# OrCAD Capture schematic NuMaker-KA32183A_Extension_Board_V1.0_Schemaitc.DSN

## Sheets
1 System_Block_Diagram: title: Block Diagram; rev: v1.1; note: NuMaker-M483SG-KA32183A
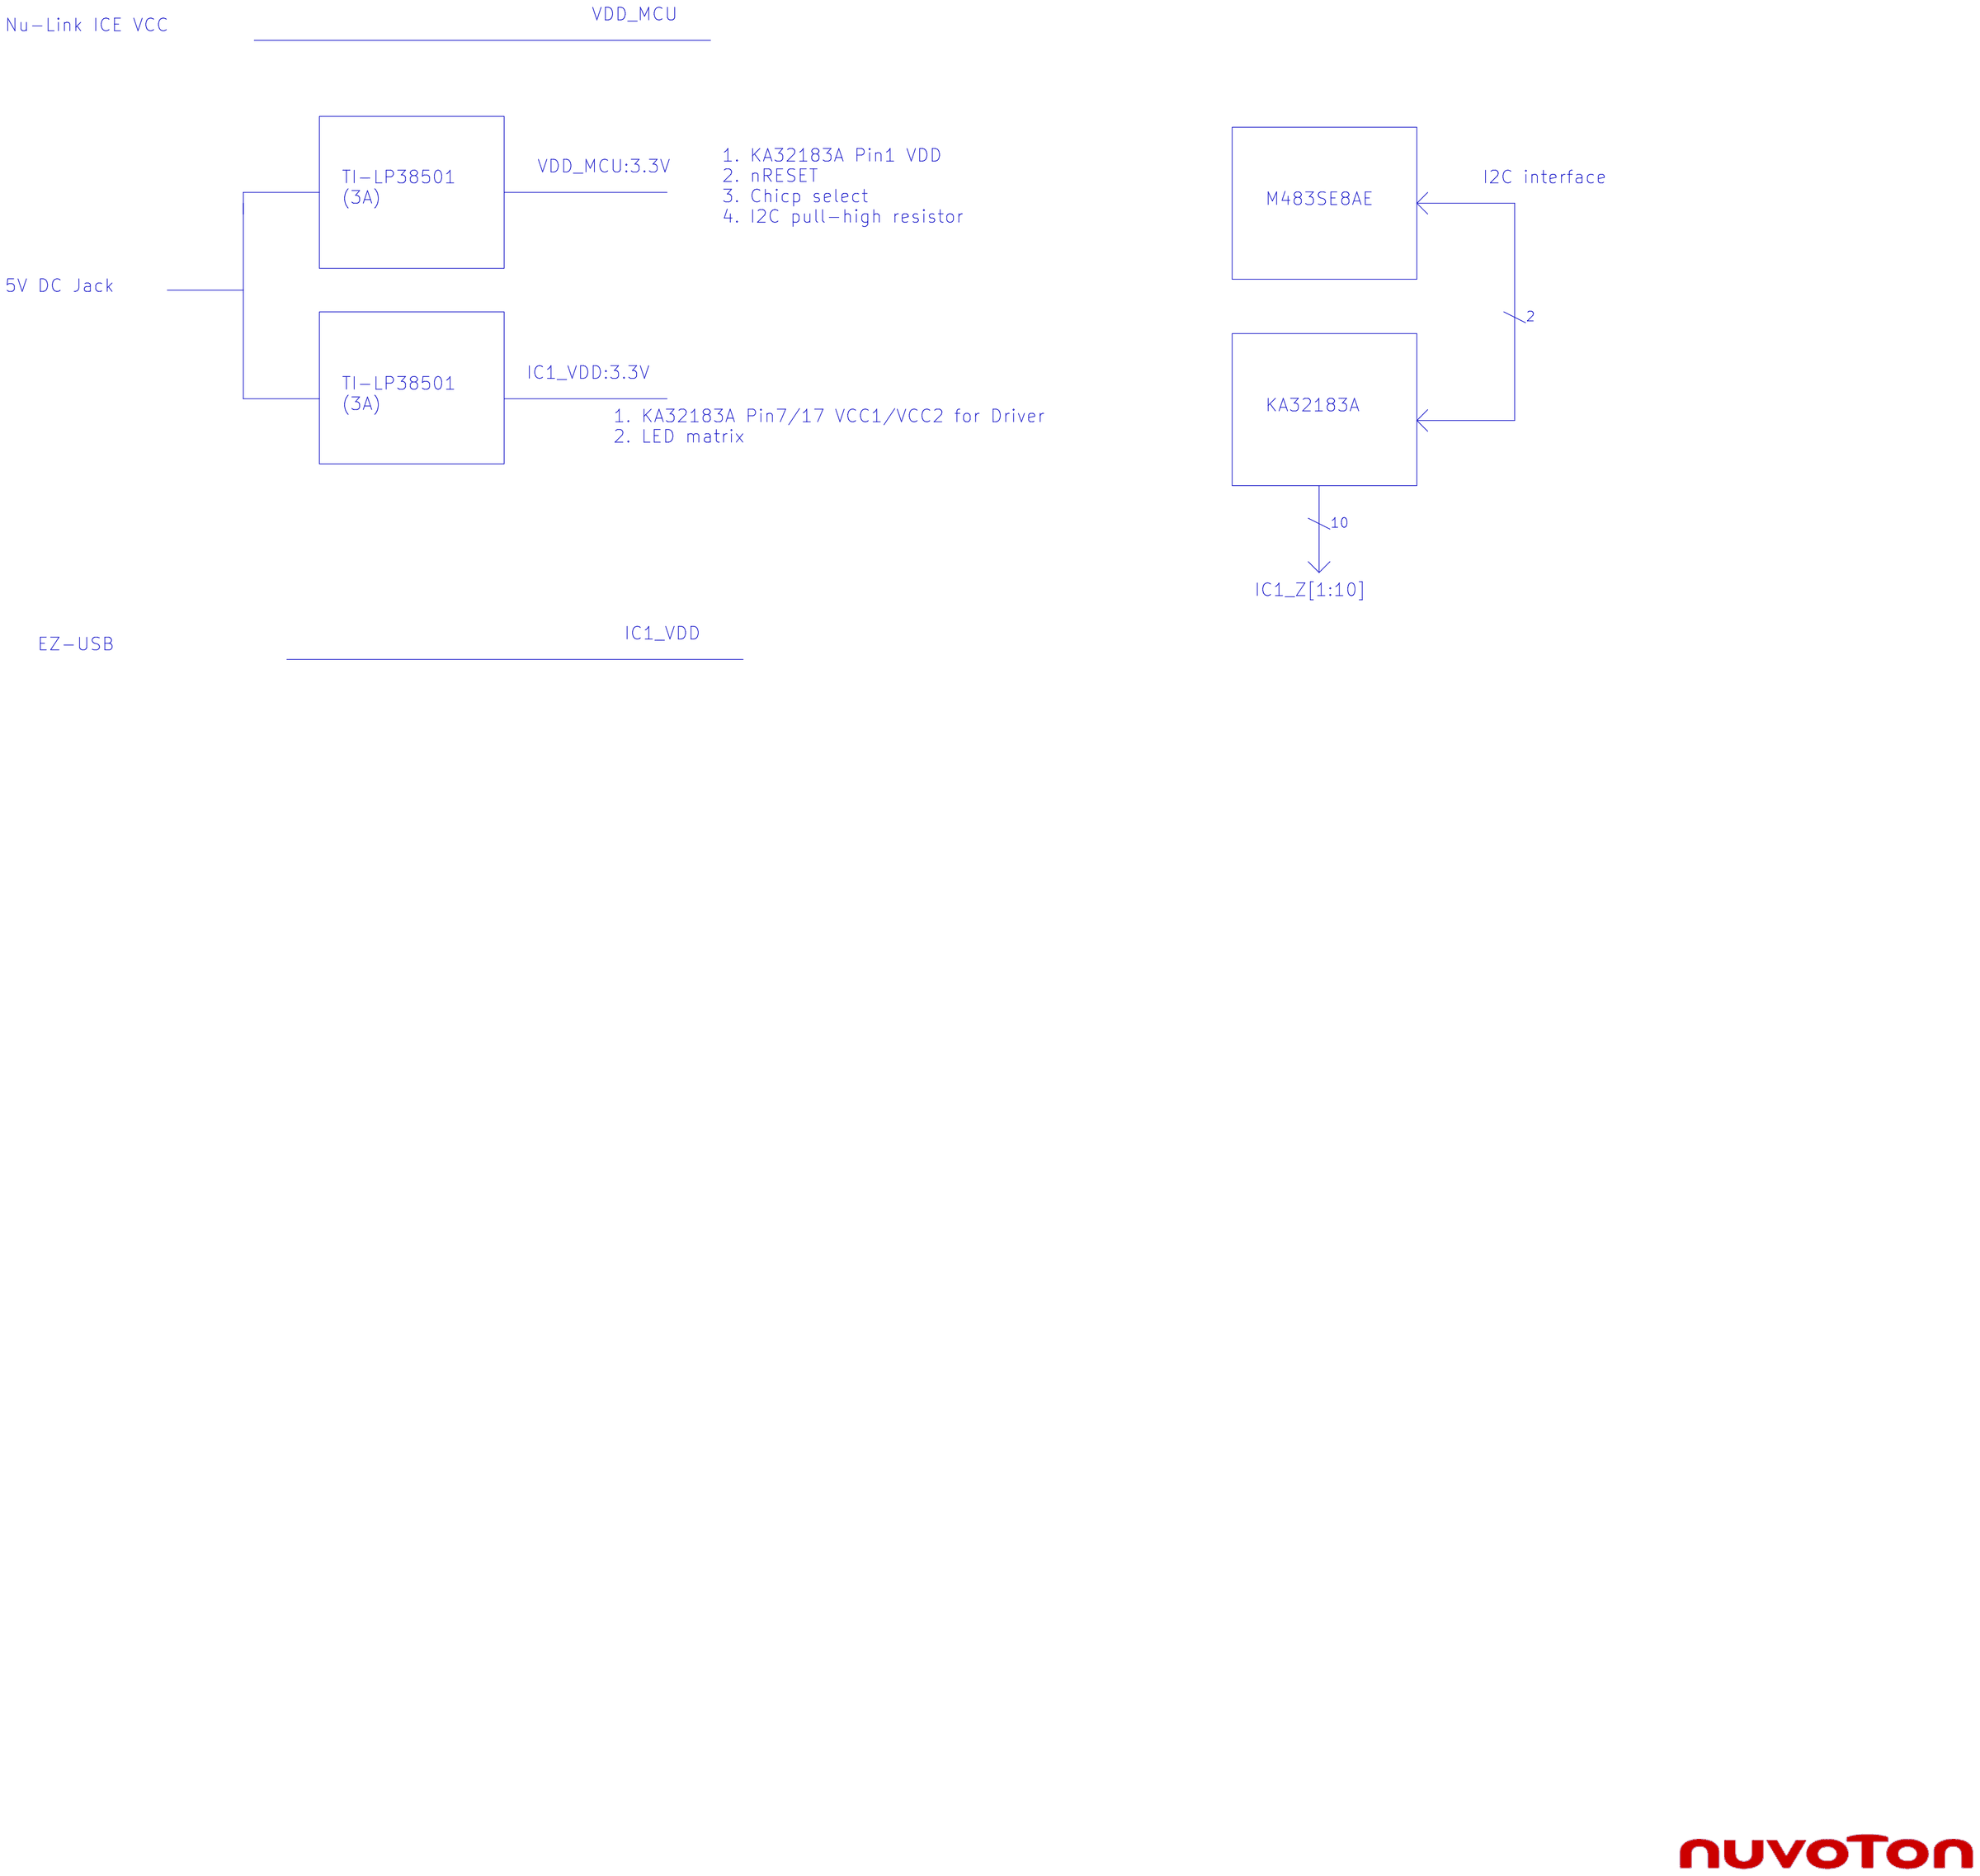
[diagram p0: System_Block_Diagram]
2 Power: size Custom; title: Power Block; note: NuMaker-M483KG-KA32183A
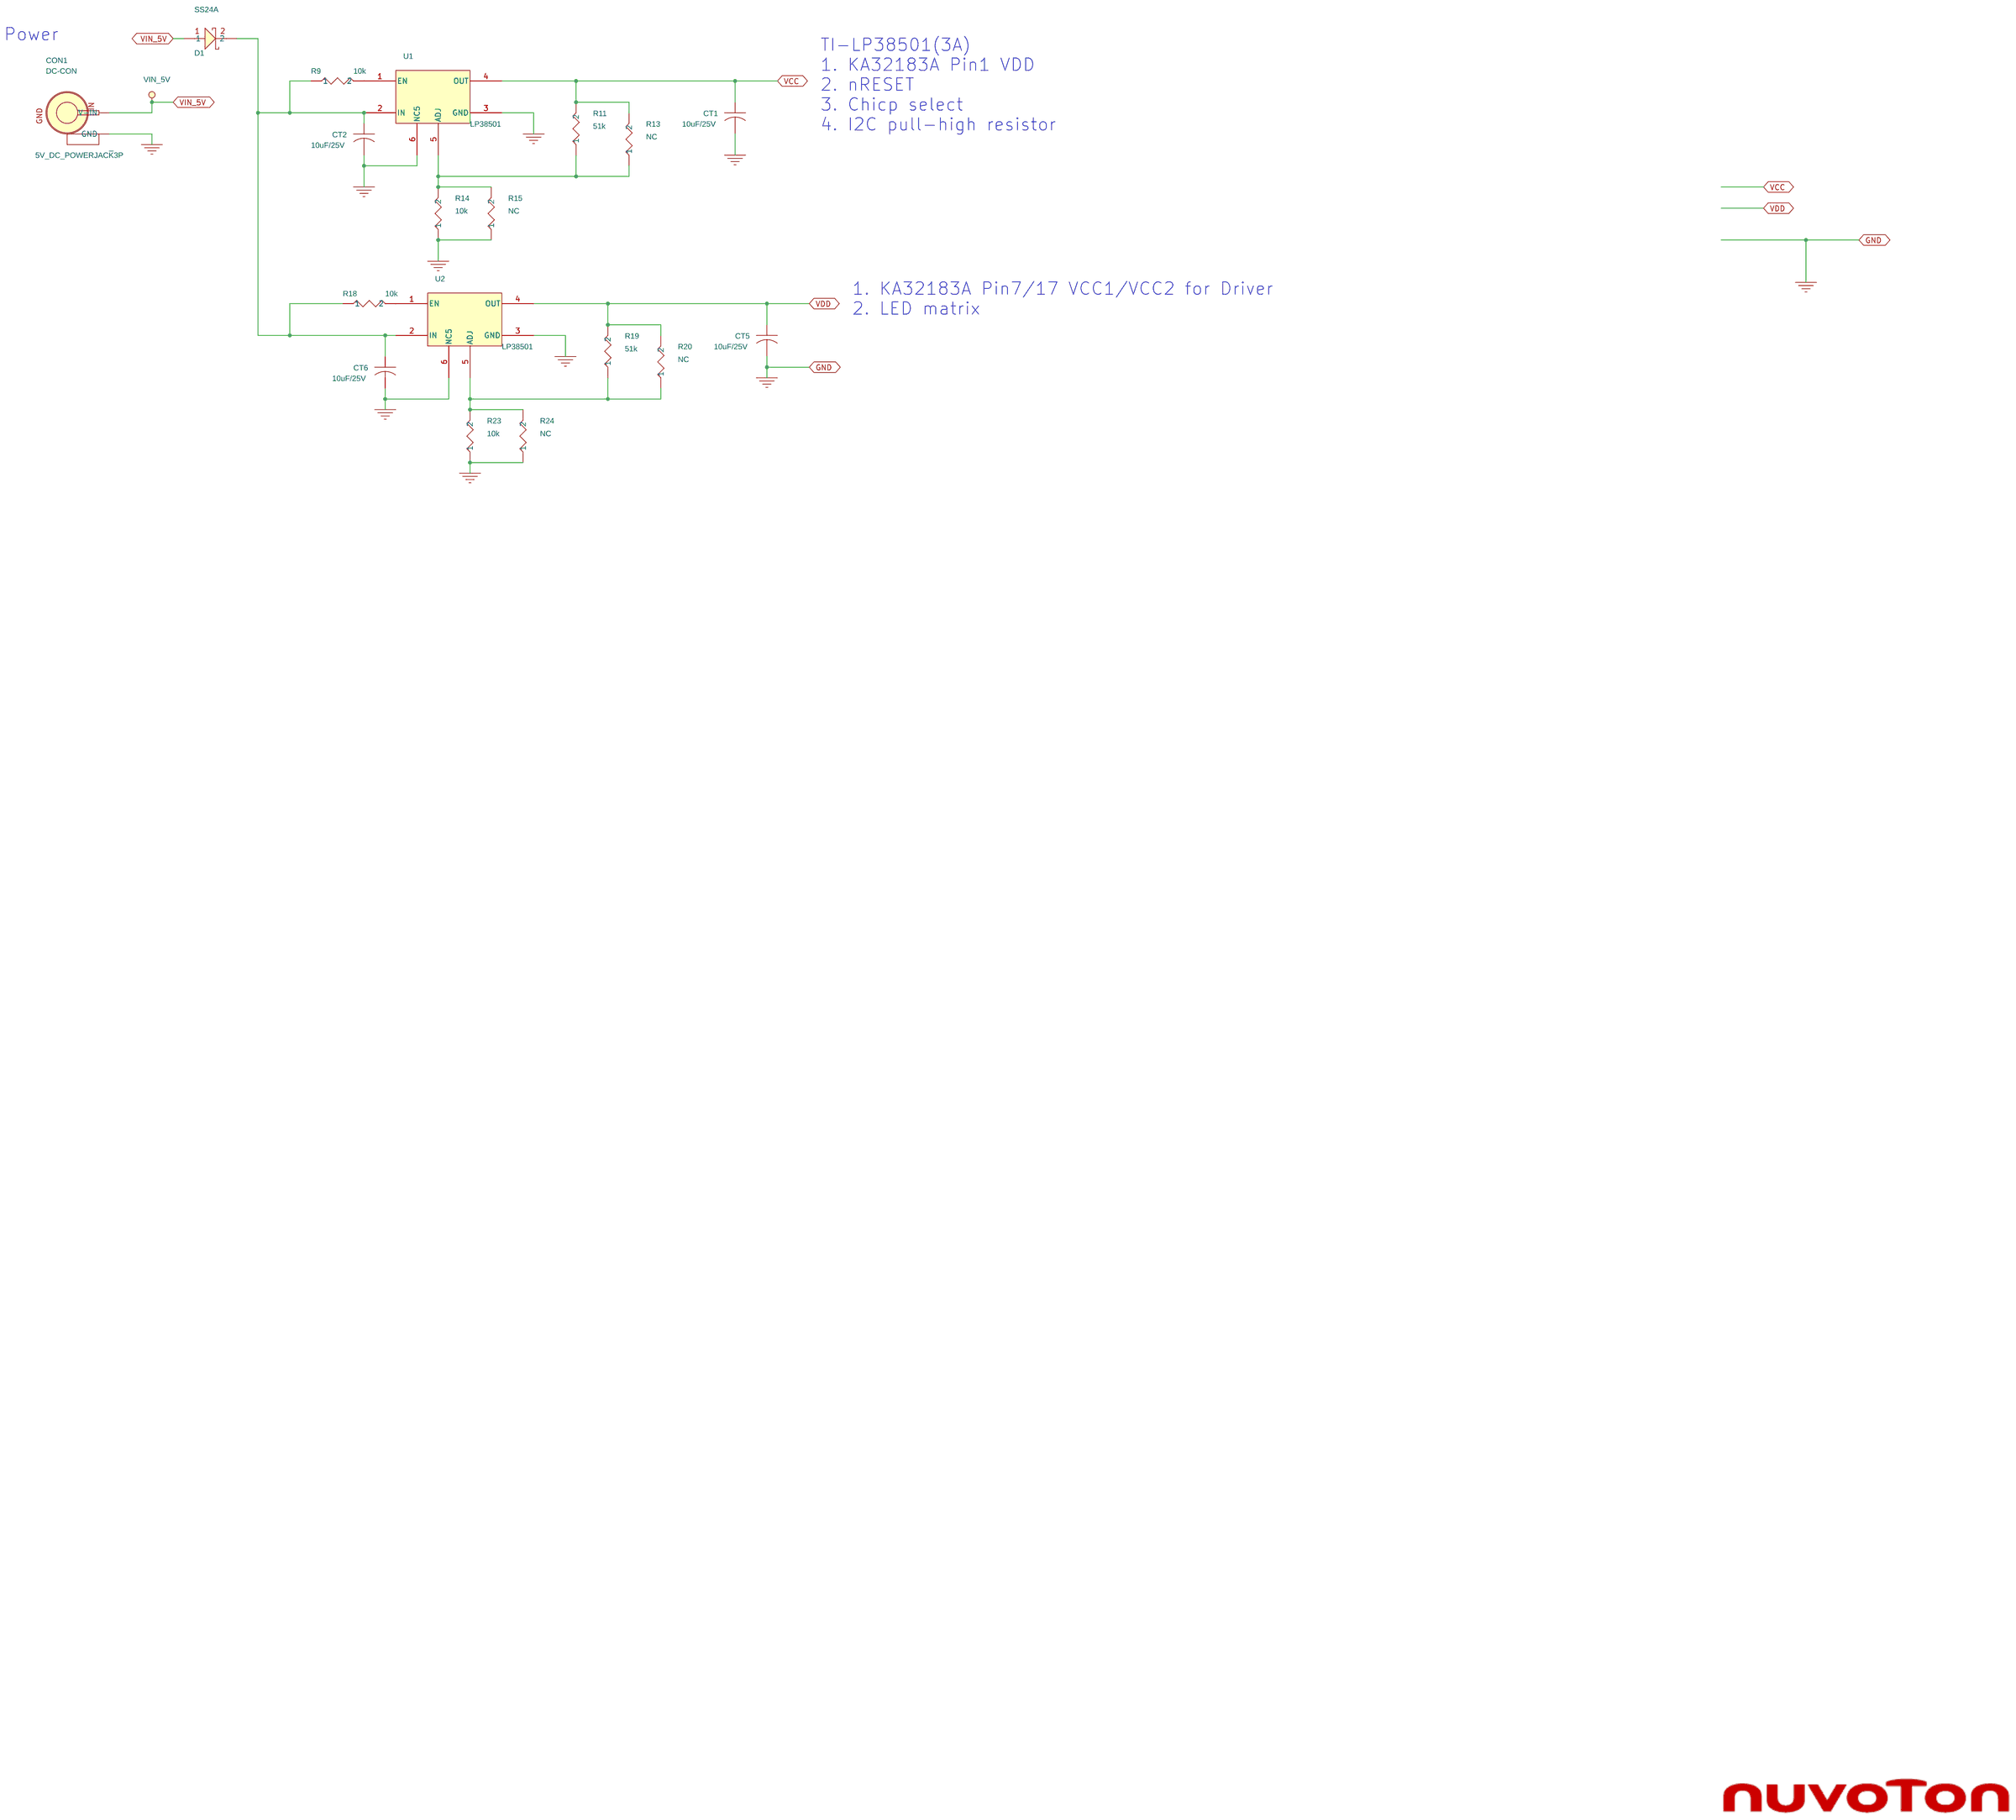
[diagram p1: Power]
3 Ext. Connector: size Custom; title: M483KGCAE2A Ext. Connector; note: NuMaker-M483KG-KA32183A
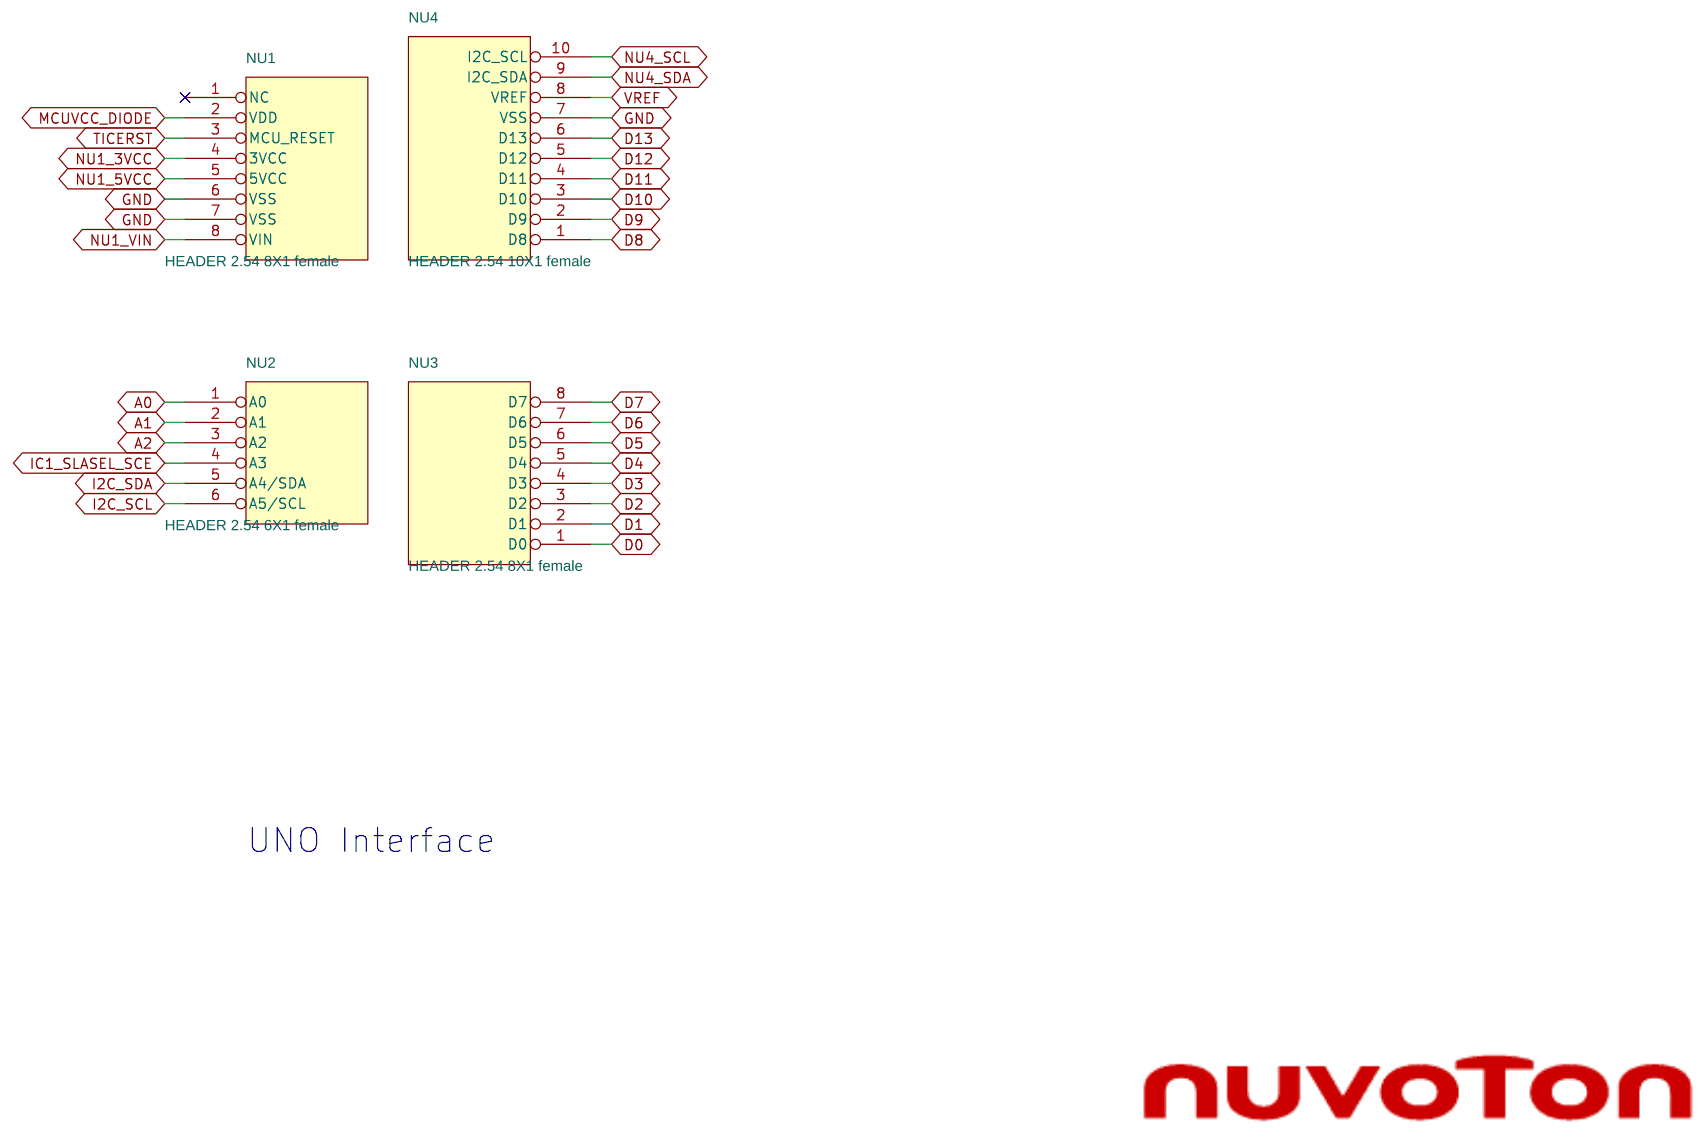
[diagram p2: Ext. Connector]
4 KA32183A: size Custom; title: KA32183A; rev: v1.0; note: NuMaker-M483KG-KA32183A
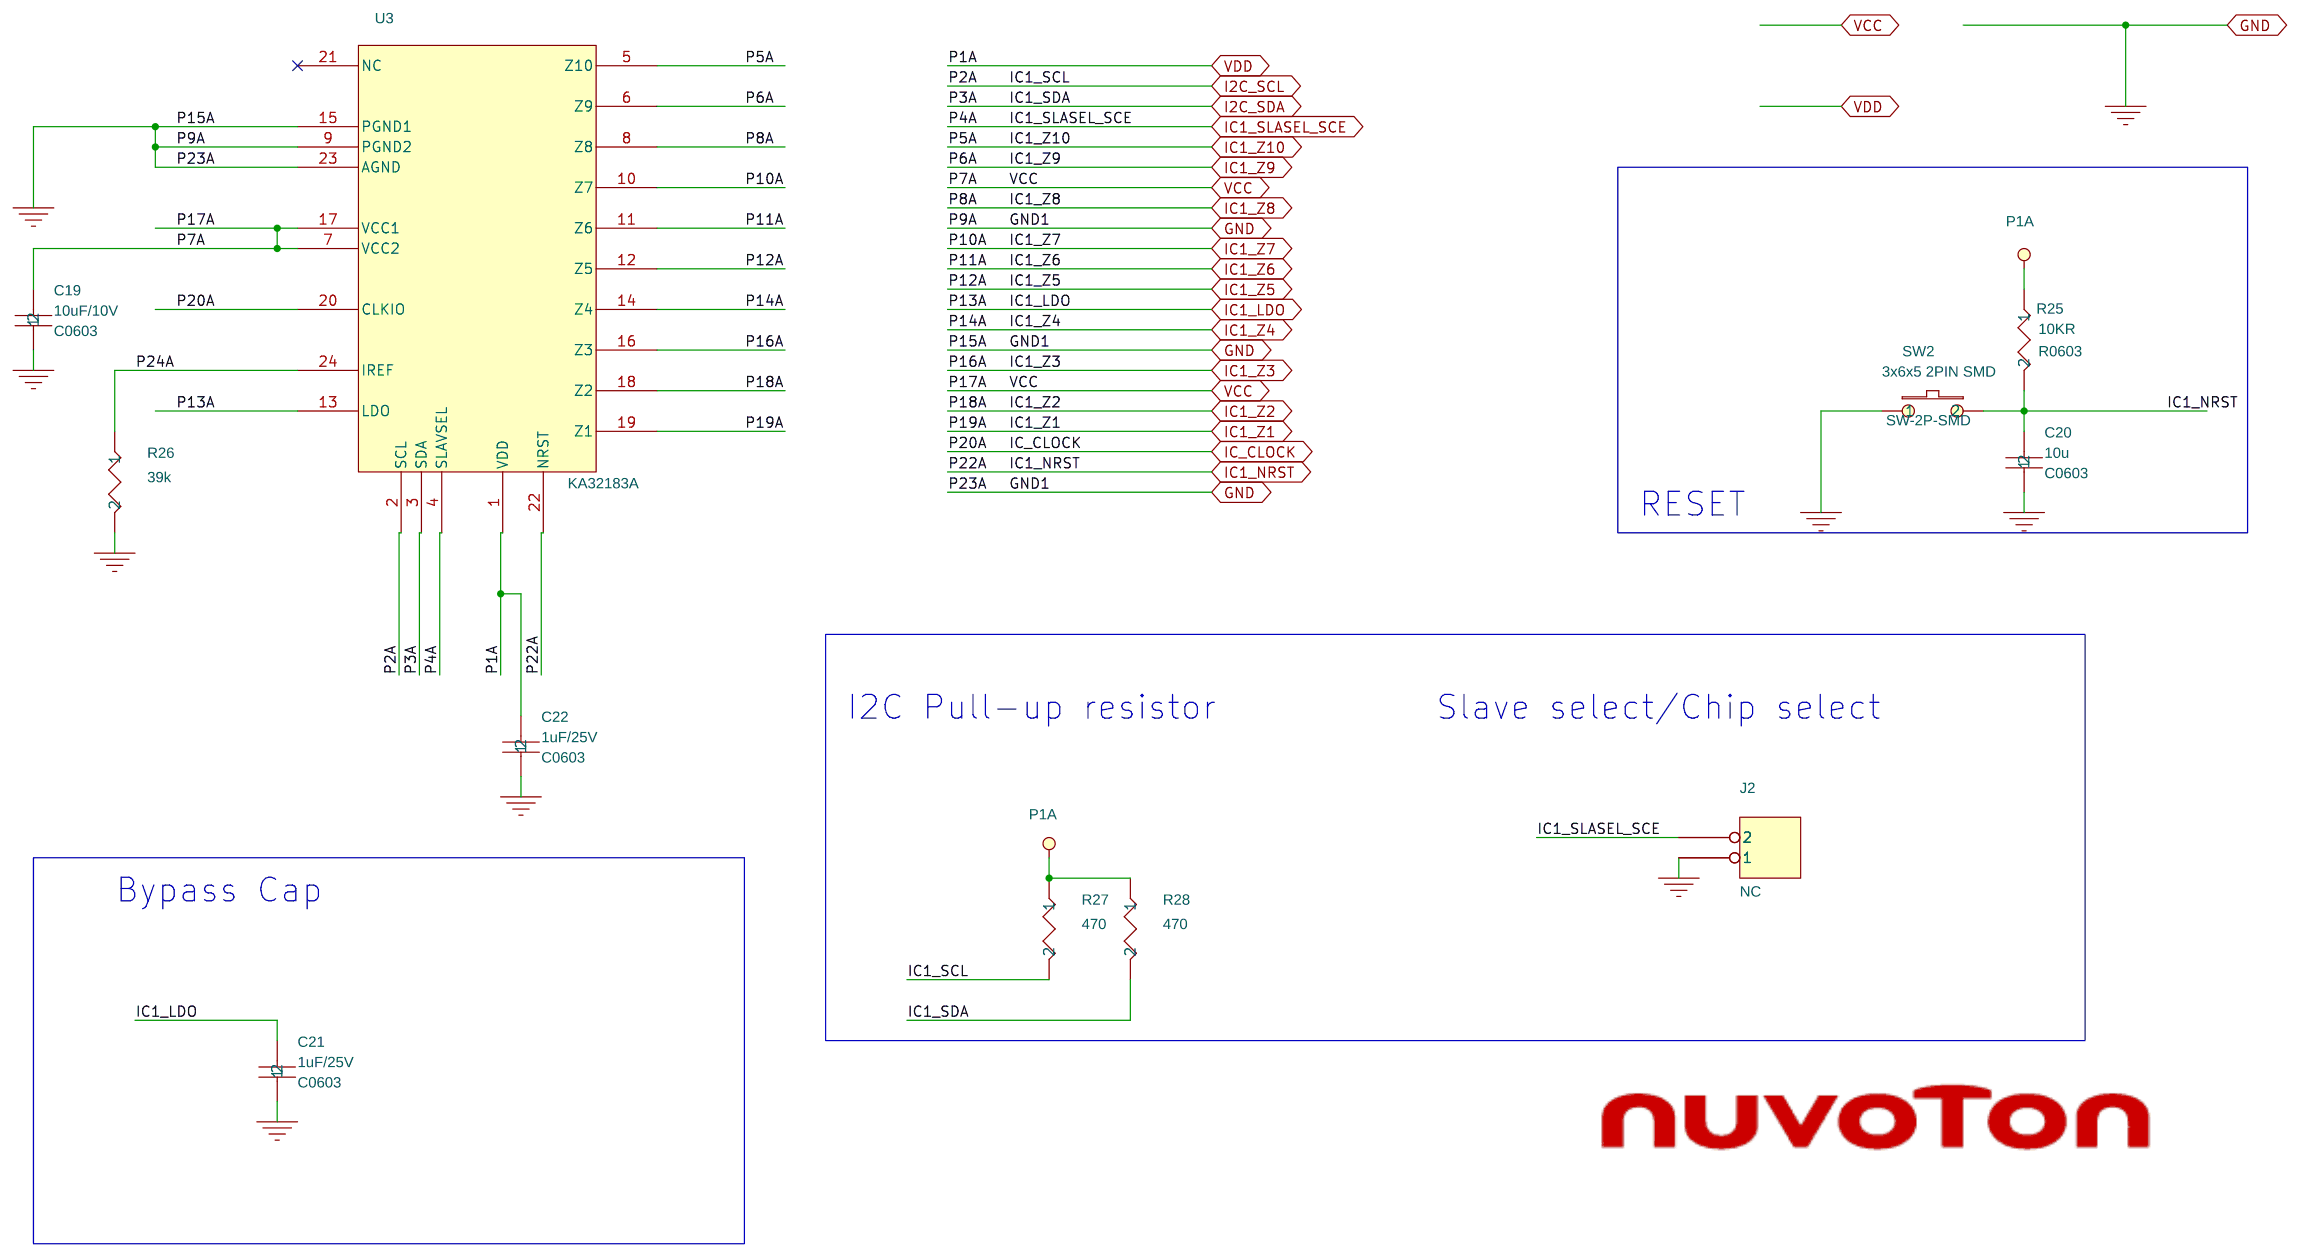
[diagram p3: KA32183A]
5 EZ_USB: size Custom; title: Hailege EZ-USB FX2LP
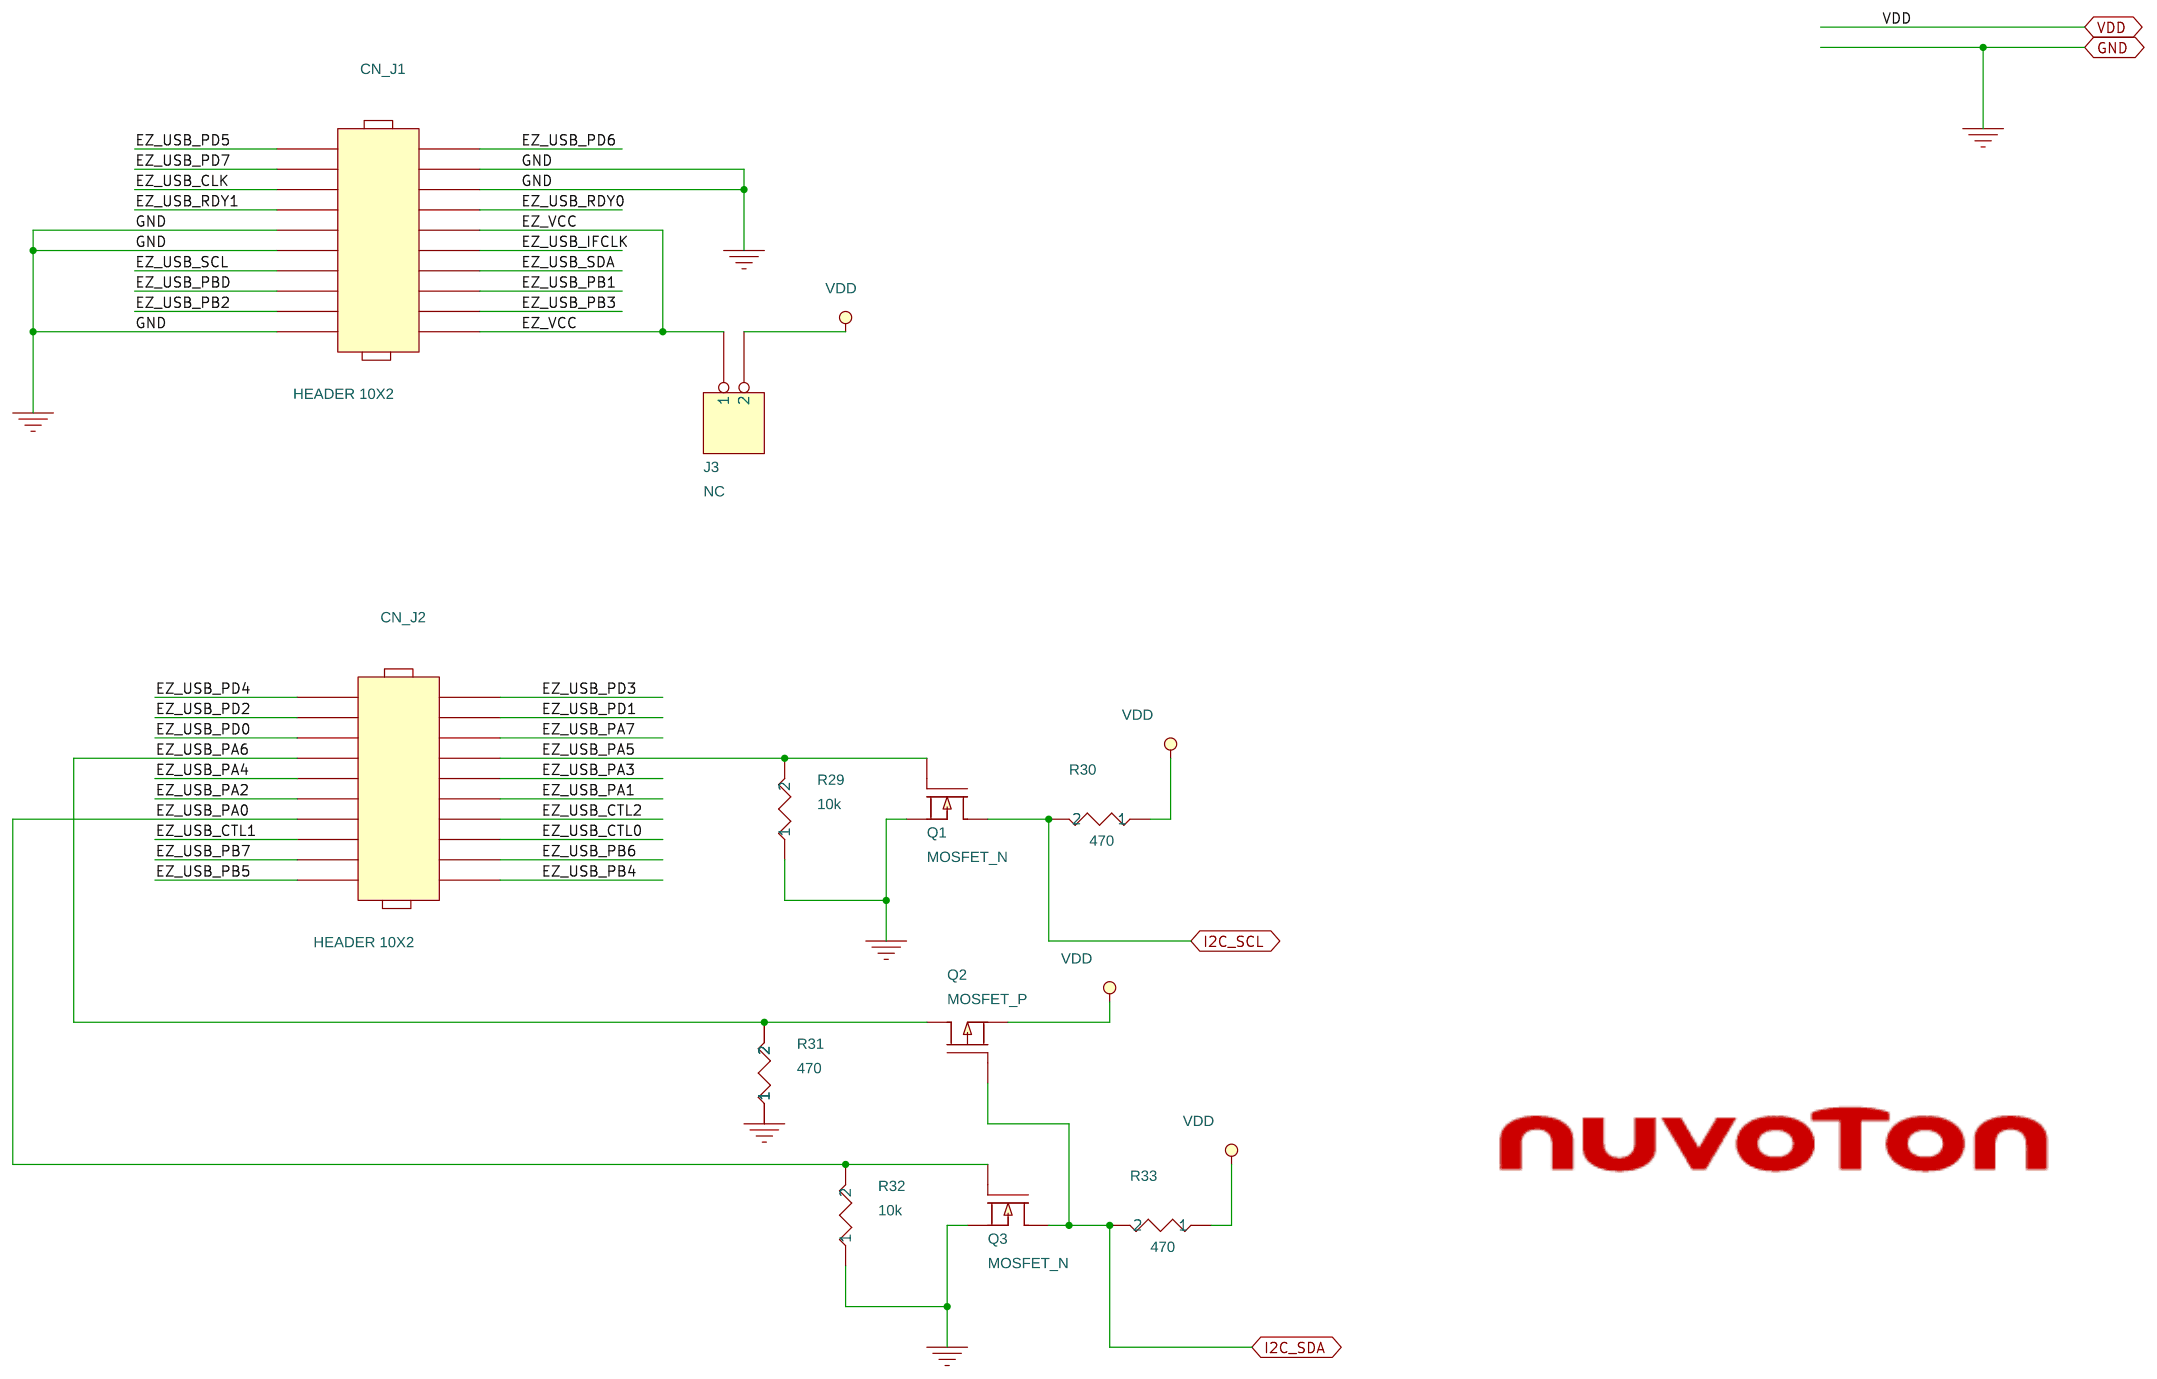
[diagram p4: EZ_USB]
6 06_Matrix_LED: size Custom; title: KA32183A LED Matrix; rev: v1.0; note: NuMaker-M483KG-KA32183A
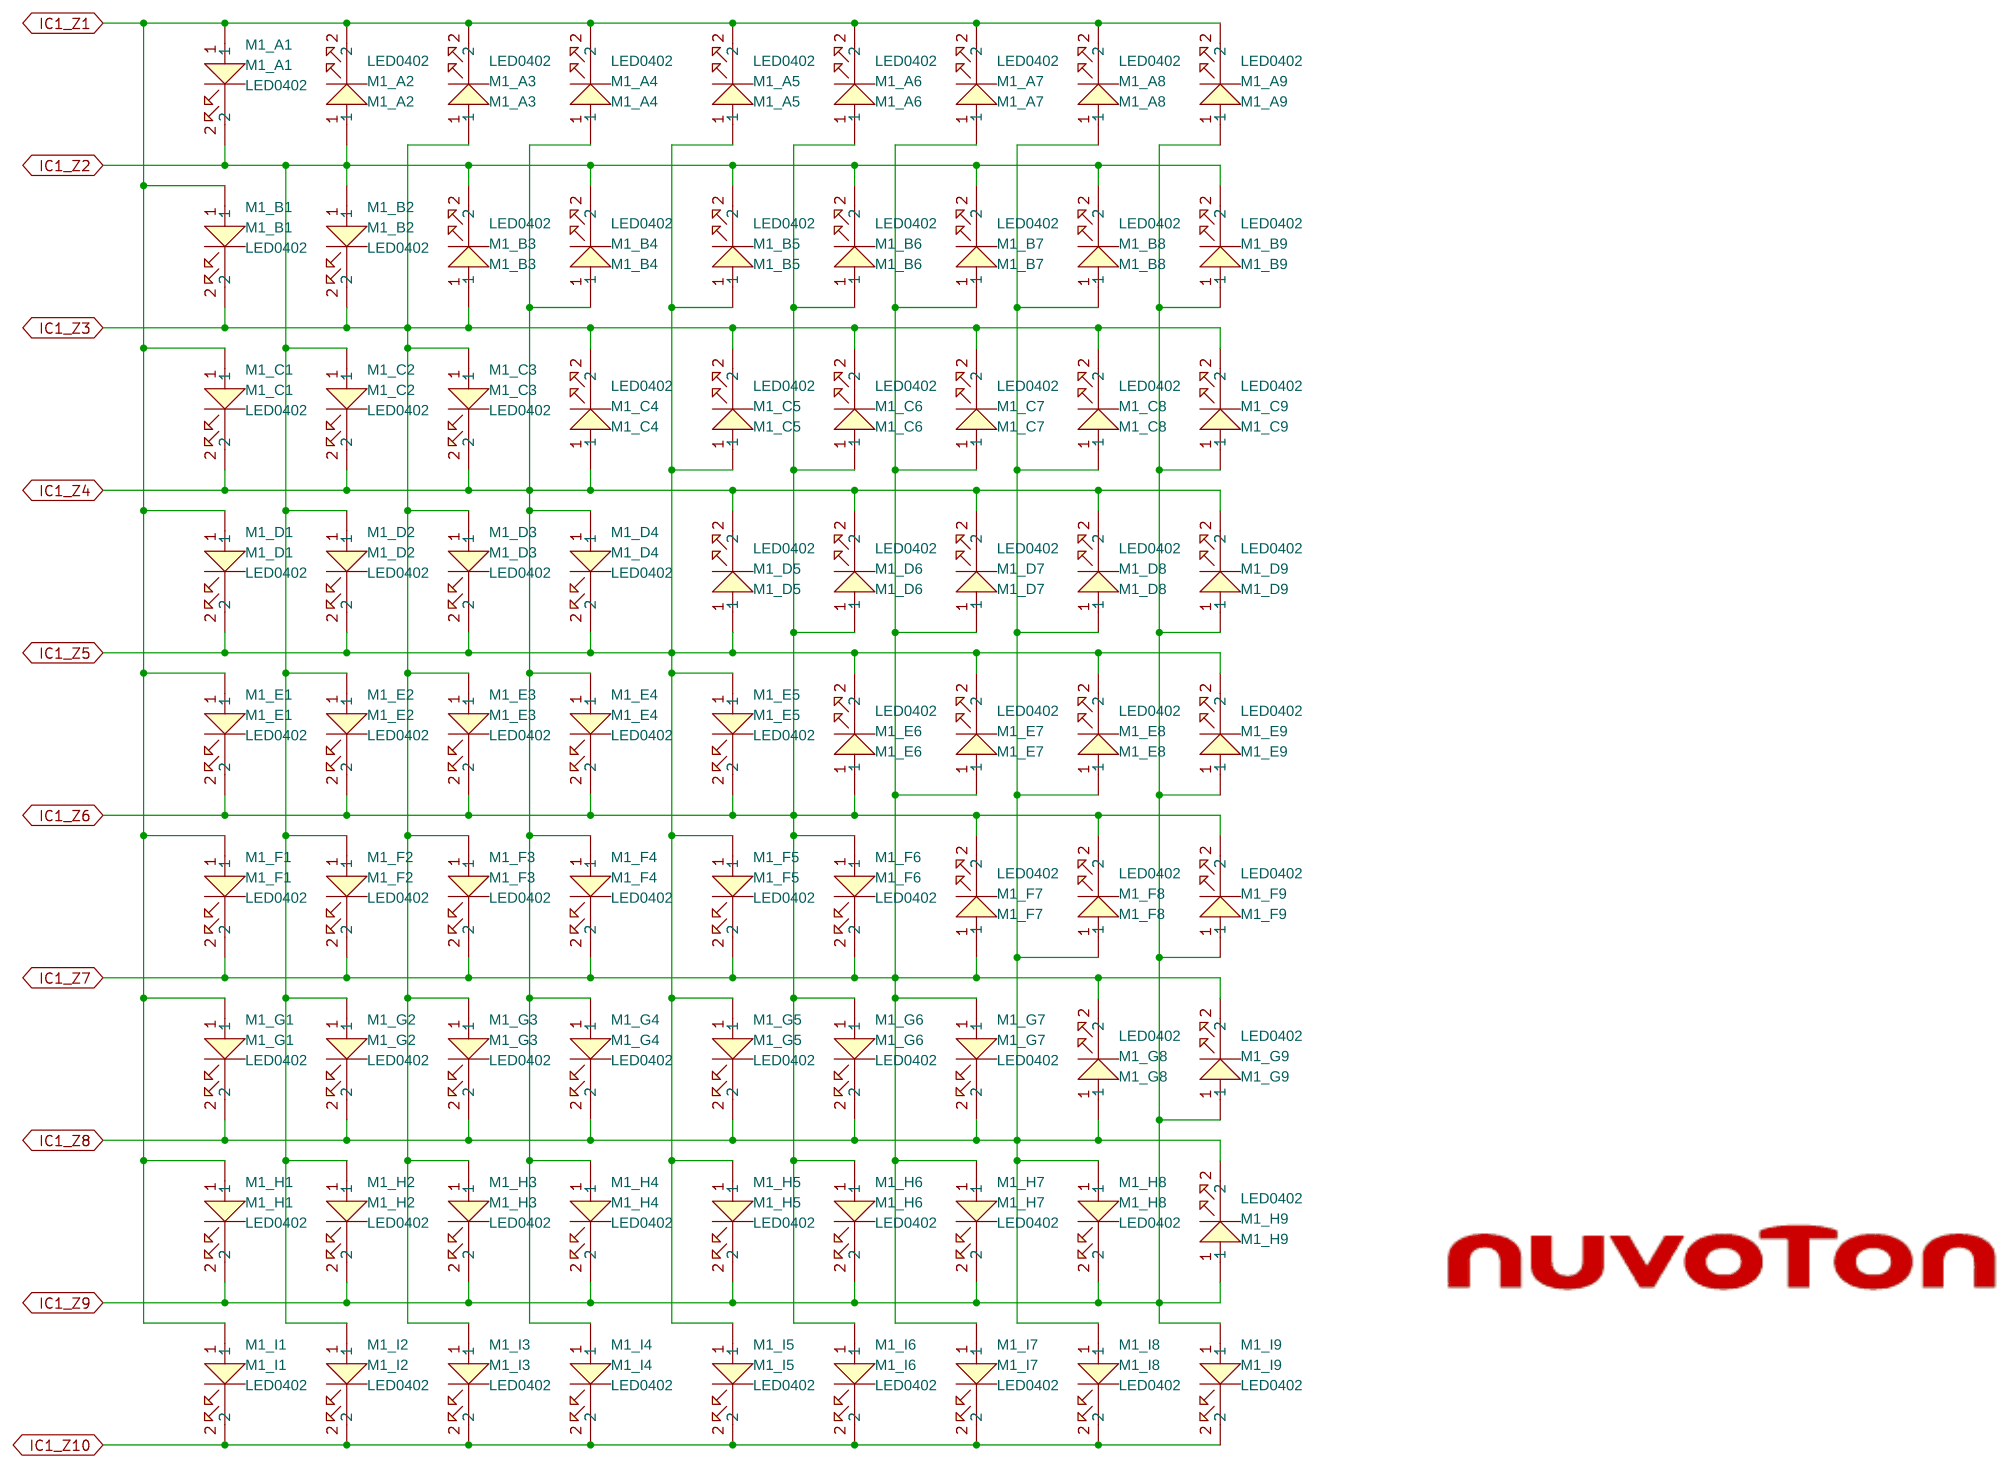
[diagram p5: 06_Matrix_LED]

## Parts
sheet 06_Matrix_LED
M1_A1  M1_A1  [LED0402]
M1_A2  M1_A2  [LED0402]
M1_A3  M1_A3  [LED0402]
M1_A4  M1_A4  [LED0402]
M1_A5  M1_A5  [LED0402]
M1_A6  M1_A6  [LED0402]
M1_A7  M1_A7  [LED0402]
M1_A8  M1_A8  [LED0402]
M1_A9  M1_A9  [LED0402]
M1_B1  M1_B1  [LED0402]
M1_B2  M1_B2  [LED0402]
M1_B3  M1_B3  [LED0402]
M1_B4  M1_B4  [LED0402]
M1_B5  M1_B5  [LED0402]
M1_B6  M1_B6  [LED0402]
M1_B7  M1_B7  [LED0402]
M1_B8  M1_B8  [LED0402]
M1_B9  M1_B9  [LED0402]
M1_C1  M1_C1  [LED0402]
M1_C2  M1_C2  [LED0402]
M1_C3  M1_C3  [LED0402]
M1_C4  M1_C4  [LED0402]
M1_C5  M1_C5  [LED0402]
M1_C6  M1_C6  [LED0402]
M1_C7  M1_C7  [LED0402]
M1_C8  M1_C8  [LED0402]
M1_C9  M1_C9  [LED0402]
M1_D1  M1_D1  [LED0402]
M1_D2  M1_D2  [LED0402]
M1_D3  M1_D3  [LED0402]
M1_D4  M1_D4  [LED0402]
M1_D5  M1_D5  [LED0402]
M1_D6  M1_D6  [LED0402]
M1_D7  M1_D7  [LED0402]
M1_D8  M1_D8  [LED0402]
M1_D9  M1_D9  [LED0402]
M1_E1  M1_E1  [LED0402]
M1_E2  M1_E2  [LED0402]
M1_E3  M1_E3  [LED0402]
M1_E4  M1_E4  [LED0402]
M1_E5  M1_E5  [LED0402]
M1_E6  M1_E6  [LED0402]
M1_E7  M1_E7  [LED0402]
M1_E8  M1_E8  [LED0402]
M1_E9  M1_E9  [LED0402]
M1_F1  M1_F1  [LED0402]
M1_F2  M1_F2  [LED0402]
M1_F3  M1_F3  [LED0402]
M1_F4  M1_F4  [LED0402]
M1_F5  M1_F5  [LED0402]
M1_F6  M1_F6  [LED0402]
M1_F7  M1_F7  [LED0402]
M1_F8  M1_F8  [LED0402]
M1_F9  M1_F9  [LED0402]
M1_G1  M1_G1  [LED0402]
M1_G2  M1_G2  [LED0402]
M1_G3  M1_G3  [LED0402]
M1_G4  M1_G4  [LED0402]
M1_G5  M1_G5  [LED0402]
M1_G6  M1_G6  [LED0402]
M1_G7  M1_G7  [LED0402]
M1_G8  M1_G8  [LED0402]
M1_G9  M1_G9  [LED0402]
M1_H1  M1_H1  [LED0402]
M1_H2  M1_H2  [LED0402]
M1_H3  M1_H3  [LED0402]
M1_H4  M1_H4  [LED0402]
M1_H5  M1_H5  [LED0402]
M1_H6  M1_H6  [LED0402]
M1_H7  M1_H7  [LED0402]
M1_H8  M1_H8  [LED0402]
M1_H9  M1_H9  [LED0402]
M1_I1  M1_I1  [LED0402]
M1_I2  M1_I2  [LED0402]
M1_I3  M1_I3  [LED0402]
M1_I4  M1_I4  [LED0402]
M1_I5  M1_I5  [LED0402]
M1_I6  M1_I6  [LED0402]
M1_I7  M1_I7  [LED0402]
M1_I8  M1_I8  [LED0402]
M1_I9  M1_I9  [LED0402]
sheet Ext. Connector
NU1  HEADER 2.54 8X1 female  [SIP-8P]
NU2  HEADER 2.54 6X1 female  [SIP-6P]
NU3  HEADER 2.54 8X1 female  [SIP-8P]
NU4  HEADER 2.54 10X1 female  [SIP-10P]
sheet EZ_USB
CN_J1  HEADER 10X2  [HEADER10X2-2.54-m]
CN_J2  HEADER 10X2  [HEADER10X2-2.54-m]
J3  NC  [HEADER2X1]
Q1  MOSFET_N
Q2  MOSFET_P
Q3  MOSFET_N
R29  10k  [R0603]
R30  470  [R0603]
R31  470  [R0603]
R32  10k  [R0603]
R33  470  [R0603]
sheet KA32183A
C19  10uF/10V  [C0603]
C20  10u  [C0603]
C21  1uF/25V  [C0603]
C22  1uF/25V  [C0603]
J2  NC  [HEADER2X1]
R25  10KR  [R0603]
R26  39k  [R0603]
R27  470  [R0603]
R28  470  [R0603]
SW2  3x6x5 2PIN SMD  [SW-2P-SMD]
U3  KA32183A  [SSOP-24-0.65mm]
sheet Power
CON1  DC-CON  [5V_DC_POWERJACK\3P]
CT1  10uF/25V  [TANT-A]
CT2  10uF/25V  [TANT-A]
CT5  10uF/25V  [TANT-A]
CT6  10uF/25V  [TANT-A]
D1  SS24A  [RB060L]
R9  10k  [R0603]
R11  51k  [R0603]
R13  NC  [R0603]
R14  10k  [R0603]
R15  NC  [R0603]
R18  10k  [R0603]
R19  51k  [R0603]
R20  NC  [R0603]
R23  10k  [R0603]
R24  NC  [R0603]
U1  LP38501  [TO-263-5]
U2  LP38501  [TO-263-5]

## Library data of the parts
M1_A1 = LED_0_75: Package: KP-2012; Vendor: VishaySemiconductors
M1_A2 = LED_0_37: Package: KP-2012; Vendor: VishaySemiconductors
M1_A3 = LED_0_3: Package: KP-2012; Vendor: VishaySemiconductors
M1_A4 = LED_0_43: Package: KP-2012; Vendor: VishaySemiconductors
M1_A5 = LED_0_6: Package: KP-2012; Vendor: VishaySemiconductors
M1_A6 = LED_0_50: Package: KP-2012; Vendor: VishaySemiconductors
M1_A7 = LED_0_10: Package: KP-2012; Vendor: VishaySemiconductors
M1_A8 = LED_0_47: Package: KP-2012; Vendor: VishaySemiconductors
M1_A9 = LED_0_15: Package: KP-2012; Vendor: VishaySemiconductors
M1_B1 = LED_0_8: Package: KP-2012; Vendor: VishaySemiconductors
M1_B2 = LED_0_14: Package: KP-2012; Vendor: VishaySemiconductors
M1_B3 = LED_0_53: Package: KP-2012; Vendor: VishaySemiconductors
M1_B4 = LED_0_19: Package: KP-2012; Vendor: VishaySemiconductors
M1_B5 = LED_0_59: Package: KP-2012; Vendor: VishaySemiconductors
M1_B6 = LED_0_24: Package: KP-2012; Vendor: VishaySemiconductors
M1_B7 = LED_0_64: Package: KP-2012; Vendor: VishaySemiconductors
M1_B8 = LED_0_70: Package: KP-2012; Vendor: VishaySemiconductors
M1_B9 = LED_0_30: Package: KP-2012; Vendor: VishaySemiconductors
M1_C1 = LED_0_7: Package: KP-2012; Vendor: VishaySemiconductors
M1_C2 = LED_0_52: Package: KP-2012; Vendor: VishaySemiconductors
M1_C3 = LED_0_13: Package: KP-2012; Vendor: VishaySemiconductors
M1_C4 = LED_0_17: Package: KP-2012; Vendor: VishaySemiconductors
M1_C5 = LED_0_57: Package: KP-2012; Vendor: VishaySemiconductors
M1_C6 = LED_0_65: Package: KP-2012; Vendor: VishaySemiconductors
M1_C7 = LED_0_62: Package: KP-2012; Vendor: VishaySemiconductors
M1_C8 = LED_0_28: Package: KP-2012; Vendor: VishaySemiconductors
M1_C9 = LED_0_69: Package: KP-2012; Vendor: VishaySemiconductors
M1_D1 = LED_0_1: Package: KP-2012; Vendor: VishaySemiconductors
M1_D2 = LED_0_34: Package: KP-2012; Vendor: VishaySemiconductors
M1_D3 = LED_0_41: Package: KP-2012; Vendor: VishaySemiconductors
M1_D4 = LED_0_4: Package: KP-2012; Vendor: VishaySemiconductors
M1_D5 = LED_0_67: Package: KP-2012; Vendor: VishaySemiconductors
M1_D6 = LED_0_27: Package: KP-2012; Vendor: VishaySemiconductors
M1_D7 = LED_0_73: Package: KP-2012; Vendor: VishaySemiconductors
M1_D8 = LED_0_20: Package: KP-2012; Vendor: VishaySemiconductors
M1_D9 = LED_0_60: Package: KP-2012; Vendor: VishaySemiconductors
M1_E1 = LED_0_56: Package: KP-2012; Vendor: VishaySemiconductors
M1_E2 = LED_0_12: Package: KP-2012; Vendor: VishaySemiconductors
M1_E3 = LED_0_71: Package: KP-2012; Vendor: VishaySemiconductors
M1_E4 = LED_0_25: Package: KP-2012; Vendor: VishaySemiconductors
M1_E5 = LED_0_32: Package: KP-2012; Vendor: VishaySemiconductors
M1_E6 = LED_0_44: Package: KP-2012; Vendor: VishaySemiconductors
M1_E7 = LED_0_45: Package: KP-2012; Vendor: VishaySemiconductors
M1_E8 = LED_0_80: Package: KP-2012; Vendor: VishaySemiconductors
M1_E9 = LED_0_33: Package: KP-2012; Vendor: VishaySemiconductors
M1_F1 = LED_0_16: Package: KP-2012; Vendor: VishaySemiconductors
M1_F2 = LED_0_61: Package: KP-2012; Vendor: VishaySemiconductors
M1_F3 = LED_0_77: Package: KP-2012; Vendor: VishaySemiconductors
M1_F4 = LED_0_23: Package: KP-2012; Vendor: VishaySemiconductors
M1_F5 = LED_0_68: Package: KP-2012; Vendor: VishaySemiconductors
M1_F6 = LED_0_76: Package: KP-2012; Vendor: VishaySemiconductors
M1_F7 = LED_0_39: Package: KP-2012; Vendor: VishaySemiconductors
M1_F8 = LED_0_40: Package: KP-2012; Vendor: VishaySemiconductors
M1_F9 = LED_0: Package: KP-2012; Vendor: VishaySemiconductors
M1_G1 = LED_0_38: Package: KP-2012; Vendor: VishaySemiconductors
M1_G2 = LED_0_78: Package: KP-2012; Vendor: VishaySemiconductors
M1_G3 = LED_0_55: Package: KP-2012; Vendor: VishaySemiconductors
M1_G4 = LED_0_11: Package: KP-2012; Vendor: VishaySemiconductors
M1_G5 = LED_0_21: Package: KP-2012; Vendor: VishaySemiconductors
M1_G6 = LED_0_74: Package: KP-2012; Vendor: VishaySemiconductors
M1_G7 = LED_0_35: Package: KP-2012; Vendor: VishaySemiconductors
M1_G8 = LED_0_58: Package: KP-2012; Vendor: VishaySemiconductors
M1_G9 = LED_0_18: Package: KP-2012; Vendor: VishaySemiconductors
M1_H1 = LED_0_79: Package: KP-2012; Vendor: VishaySemiconductors
M1_H2 = LED_0_63: Package: KP-2012; Vendor: VishaySemiconductors
M1_H3 = LED_0_51: Package: KP-2012; Vendor: VishaySemiconductors
M1_H4 = LED_0_31: Package: KP-2012; Vendor: VishaySemiconductors
M1_H5 = LED_0_2: Package: KP-2012; Vendor: VishaySemiconductors
M1_H6 = LED_0_48: Package: KP-2012; Vendor: VishaySemiconductors
M1_H7 = LED_0_36: Package: KP-2012; Vendor: VishaySemiconductors
M1_H8 = LED_0_42: Package: KP-2012; Vendor: VishaySemiconductors
M1_H9 = LED_0_5: Package: KP-2012; Vendor: VishaySemiconductors
M1_I1 = LED_0_49: Package: KP-2012; Vendor: VishaySemiconductors
M1_I2 = LED_0_54: Package: KP-2012; Vendor: VishaySemiconductors
M1_I3 = LED_0_29: Package: KP-2012; Vendor: VishaySemiconductors
M1_I4 = LED_0_9: Package: KP-2012; Vendor: VishaySemiconductors
M1_I5 = LED_0_22: Package: KP-2012; Vendor: VishaySemiconductors
M1_I6 = LED_0_46: Package: KP-2012; Vendor: VishaySemiconductors
M1_I7 = LED_0_26: Package: KP-2012; Vendor: VishaySemiconductors
M1_I8 = LED_0_72: Package: KP-2012; Vendor: VishaySemiconductors
M1_I9 = LED_0_66: Package: KP-2012; Vendor: VishaySemiconductors
NU1 = POWER_CONNECT_0
NU2 = ADC_CONNECT_0
NU3 = PWM0_CONNECT_0
NU4 = PWM1_CONNECT_1
CN_J1 CN_J2 = HEADER_10X2
J2 J3 = HEADER_2
Q1 Q3 = MOSFET_N
Q2 = MOSFET_P
R13 R29 = R_0_4
R24 R26 R30 = R_0_1
R18 R31 = R_0_3
R20 R27 R32 = R_0
R19 R28 R33 = R_0_2
C19 = CAP-C: Package: 0603; element_no: C0006
C20 = CAP-C_1: Package: 0603; element_no: C0006
C21 = CAP-C_3: Package: 0603; element_no: C0006
C22 = CAP-C_2: Package: 0603; element_no: C0006
R25 = R_0_3: Package: 0603
SW2 = SW_PUSHBUTTON_0
U3 = KA32183A
CON1 = DC-CON_1: Package: POWERJACK\3P
CT1 CT2 CT5 CT6 = C_10uF_10V
D1 = D_SS24A
R9 = R_0_5
R11 = R_0_8
R14 = R_0_7
R15 = R_0_9
R23 = R_0_6
U1 U2 = LP38501

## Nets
GND: C19.1 C20.1 C21.1 C22.1 CN_J1.4 CN_J1.6 CN_J1.9 CN_J1.11 CN_J1.19 CON1.2(GND) CT1.2 CT2.2 CT5.2 CT6.2 J2.1 NU1.6(VSS) NU1.7(VSS) NU4.7(VSS) Q1.3(SOURCE) Q3.3(SOURCE) R14.1 R15.1 R23.1 R24.1 R26.2 R29.1 R31.1 R32.1 SW2.1 U1.3(GND) U1.6(NC5) U2.3(GND) U2.6(NC5) U3.9(PGND2) U3.15(PGND1) U3.23(AGND)
VCC: C19.2 CT1.1 R11.2 R13.2 U1.4(OUT) U3.7(VCC2) U3.17(VCC1)
VDD: C22.2 CT5.1 J3.2 Q2.3(SOURCE) R19.2 R20.2 R25.1 R27.1 R28.1 R30.1 R33.1 U2.4(OUT) U3.1(VDD)
VIN_5V: CON1.1(V-IN) D1.1
A0: NU2.1(A0)
A1: NU2.2(A1)
A2: NU2.3(A2)
D0: NU3.1(D0)
D1: NU3.2(D1)
D2: NU3.3(D2)
D3: NU3.4(D3)
D4: NU3.5(D4)
D5: NU3.6(D5)
D6: NU3.7(D6)
D7: NU3.8(D7)
D8: NU4.1(D8)
D9: NU4.2(D9)
D10: NU4.3(D10)
D11: NU4.4(D11)
D12: NU4.5(D12)
D13: NU4.6(D13)
EZ_USB_CLK: CN_J1.5
EZ_USB_CTL0: CN_J2.16
EZ_USB_CTL1: CN_J2.15
EZ_USB_CTL2: CN_J2.14
EZ_USB_IFCLK: CN_J1.12
EZ_USB_PA0: CN_J2.13 Q3.1(GATE) R32.2
EZ_USB_PA1: CN_J2.12
EZ_USB_PA2: CN_J2.11
EZ_USB_PA3: CN_J2.10
EZ_USB_PA4: CN_J2.9
EZ_USB_PA5: CN_J2.8 Q1.1(GATE) R29.2
EZ_USB_PA6: CN_J2.7 Q2.2(DRAIN) R31.2
EZ_USB_PA7: CN_J2.6
EZ_USB_PB1: CN_J1.16
EZ_USB_PB2: CN_J1.17
EZ_USB_PB3: CN_J1.18
EZ_USB_PB4: CN_J2.20
EZ_USB_PB5: CN_J2.19
EZ_USB_PB6: CN_J2.18
EZ_USB_PB7: CN_J2.17
EZ_USB_PBD: CN_J1.15
EZ_USB_PD0: CN_J2.5
EZ_USB_PD1: CN_J2.4
EZ_USB_PD2: CN_J2.3
EZ_USB_PD3: CN_J2.2
EZ_USB_PD4: CN_J2.1
EZ_USB_PD5: CN_J1.1
EZ_USB_PD6: CN_J1.2
EZ_USB_PD7: CN_J1.3
EZ_USB_RDY0: CN_J1.8
EZ_USB_RDY1: CN_J1.7
EZ_USB_SCL: CN_J1.13
EZ_USB_SDA: CN_J1.14
EZ_VCC: CN_J1.10 CN_J1.20 J3.1
I2C_SCL: NU2.6(A5/SCL) Q1.2(DRAIN) R27.2 R30.2 U3.2(SCL)
I2C_SDA: NU2.5(A4/SDA) Q2.1(GATE) Q3.2(DRAIN) R28.2 R33.2 U3.3(SDA)
IC1_LDO: C21.2 U3.13(LDO)
IC1_NRST: C20.2 R25.2 SW2.2 U3.22(NRST)
IC1_SLASEL_SCE: J2.2 NU2.4(A3) U3.4(SLAVSEL)
IC1_Z1: M1_A1.1 M1_A2.2 M1_A3.2 M1_A4.2 M1_A5.2 M1_A6.2 M1_A7.2 M1_A8.2 M1_A9.2 M1_B1.1 M1_C1.1 M1_D1.1 M1_E1.1 M1_F1.1 M1_G1.1 M1_H1.1 M1_I1.1 U3.19(Z1)
IC1_Z2: M1_A1.2 M1_A2.1 M1_B2.1 M1_B3.2 M1_B4.2 M1_B5.2 M1_B6.2 M1_B7.2 M1_B8.2 M1_B9.2 M1_C2.1 M1_D2.1 M1_E2.1 M1_F2.1 M1_G2.1 M1_H2.1 M1_I2.1 U3.18(Z2)
IC1_Z3: M1_A3.1 M1_B1.2 M1_B2.2 M1_B3.1 M1_C3.1 M1_C4.2 M1_C5.2 M1_C6.2 M1_C7.2 M1_C8.2 M1_C9.2 M1_D3.1 M1_E3.1 M1_F3.1 M1_G3.1 M1_H3.1 M1_I3.1 U3.16(Z3)
IC1_Z4: M1_A4.1 M1_B4.1 M1_C1.2 M1_C2.2 M1_C3.2 M1_C4.1 M1_D4.1 M1_D5.2 M1_D6.2 M1_D7.2 M1_D8.2 M1_D9.2 M1_E4.1 M1_F4.1 M1_G4.1 M1_H4.1 M1_I4.1 U3.14(Z4)
IC1_Z5: M1_A5.1 M1_B5.1 M1_C5.1 M1_D1.2 M1_D2.2 M1_D3.2 M1_D4.2 M1_D5.1 M1_E5.1 M1_E6.2 M1_E7.2 M1_E8.2 M1_E9.2 M1_F5.1 M1_G5.1 M1_H5.1 M1_I5.1 U3.12(Z5)
IC1_Z6: M1_A6.1 M1_B6.1 M1_C6.1 M1_D6.1 M1_E1.2 M1_E2.2 M1_E3.2 M1_E4.2 M1_E5.2 M1_E6.1 M1_F6.1 M1_F7.2 M1_F8.2 M1_F9.2 M1_G6.1 M1_H6.1 M1_I6.1 U3.11(Z6)
IC1_Z7: M1_A7.1 M1_B7.1 M1_C7.1 M1_D7.1 M1_E7.1 M1_F1.2 M1_F2.2 M1_F3.2 M1_F4.2 M1_F5.2 M1_F6.2 M1_F7.1 M1_G7.1 M1_G8.2 M1_G9.2 M1_H7.1 M1_I7.1 U3.10(Z7)
IC1_Z8: M1_A8.1 M1_B8.1 M1_C8.1 M1_D8.1 M1_E8.1 M1_F8.1 M1_G1.2 M1_G2.2 M1_G3.2 M1_G4.2 M1_G5.2 M1_G6.2 M1_G7.2 M1_G8.1 M1_H8.1 M1_H9.2 M1_I8.1 U3.8(Z8)
IC1_Z9: M1_A9.1 M1_B9.1 M1_C9.1 M1_D9.1 M1_E9.1 M1_F9.1 M1_G9.1 M1_H1.2 M1_H2.2 M1_H3.2 M1_H4.2 M1_H5.2 M1_H6.2 M1_H7.2 M1_H8.2 M1_H9.1 M1_I9.1 U3.6(Z9)
IC1_Z10: M1_I1.2 M1_I2.2 M1_I3.2 M1_I4.2 M1_I5.2 M1_I6.2 M1_I7.2 M1_I8.2 M1_I9.2 U3.5(Z10)
IC_CLOCK: U3.20(CLKIO)
MCUVCC_DIODE: NU1.2(VDD)
NU1_3VCC: NU1.4(3VCC)
NU1_5VCC: NU1.5(5VCC)
NU1_VIN: NU1.8(VIN)
NU4_SCL: NU4.10(I2C_SCL)
NU4_SDA: NU4.9(I2C_SDA)
P24A: R26.1 U3.24(IREF)
TICERST: NU1.3(MCU_RESET)
VREF: NU4.8(VREF)
N17431251: CT2.1 CT6.1 D1.2 R9.1 R18.1 U1.2(IN) U2.2(IN)
N17431360: R19.1 R20.1 R23.2 R24.2 U2.5(ADJ)
N17431398: R11.1 R13.1 R14.2 R15.2 U1.5(ADJ)
N17445955: R18.2 U2.1(EN)
N17445956: R9.2 U1.1(EN)

Not connected (* = marked no-connect by the designer): NU1 1(NC)*; U3 21(NC)*

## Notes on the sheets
sheet 1
- VDD_MCU
- Nu-Link ICE VCC
- 1. KA32183A Pin1 VDD
  2. nRESET
  3. Chicp select
  4. I2C pull-high resistor
- TI-LP38501
  (3A)
- VDD_MCU:3.3V
- I2C interface
- M483SE8AE
- 5V DC Jack
- 2
- IC1_VDD:3.3V
- TI-LP38501
  (3A)
- KA32183A
- 1. KA32183A Pin7/17 VCC1/VCC2 for Driver
  2. LED matrix
- 10
- IC1_Z[1:10]
- IC1_VDD
- EZ-USB
sheet 2
- Power
- TI-LP38501(3A)
  1. KA32183A Pin1 VDD
  2. nRESET
  3. Chicp select
  4. I2C pull-high resistor
- 1. KA32183A Pin7/17 VCC1/VCC2 for Driver
  2. LED matrix
sheet 3
- UNO Interface
sheet 4
- RESET
- I2C Pull-up resistor
- Slave select/Chip select
- Bypass Cap
